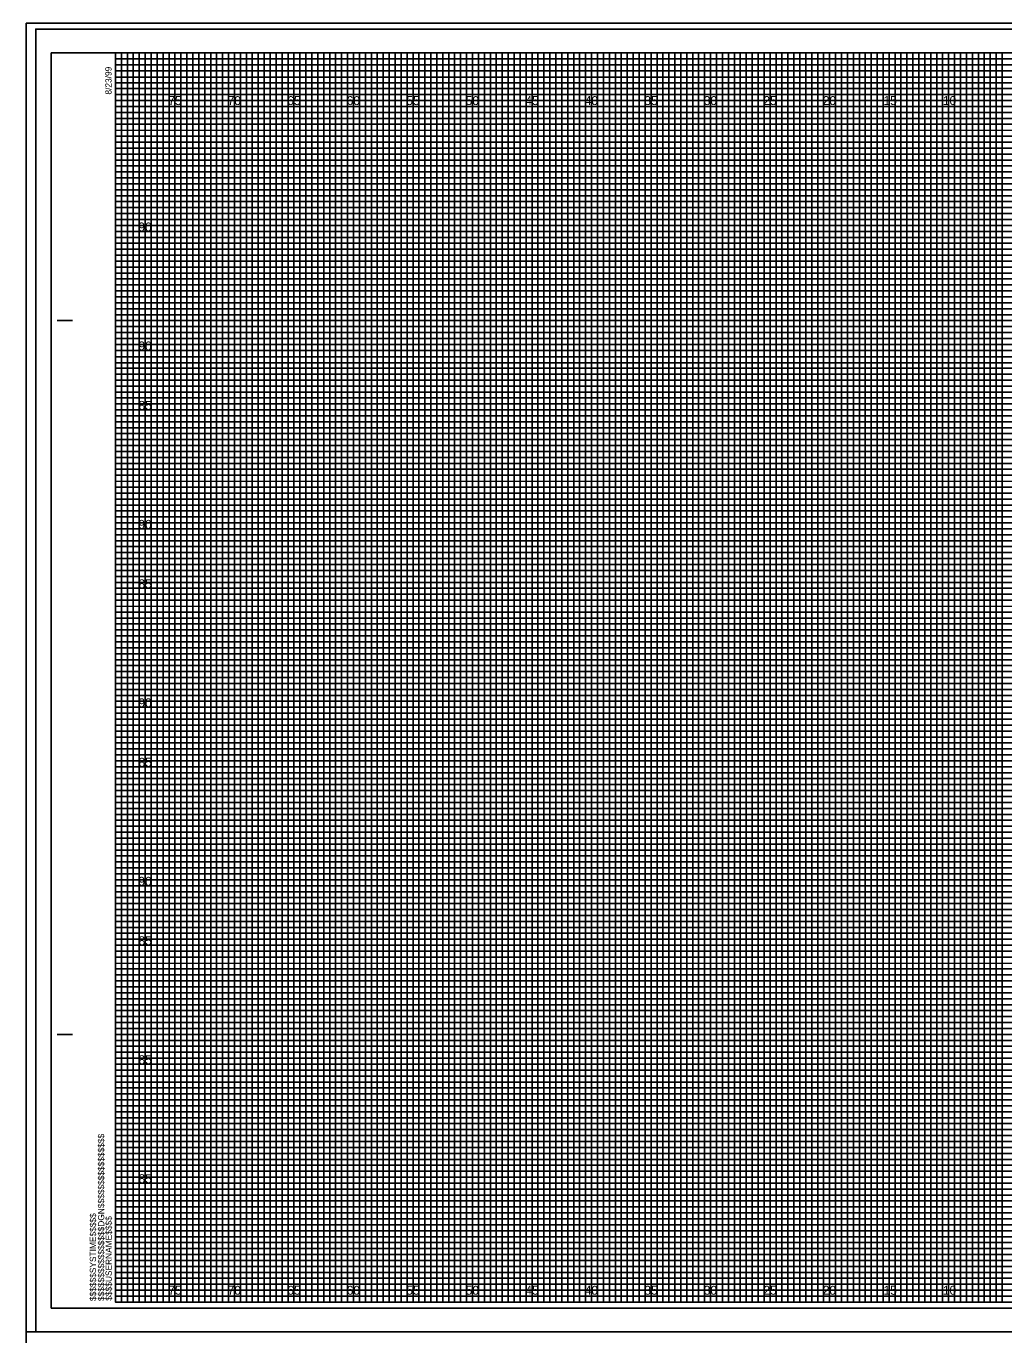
# Model space of a CAD drawing. Extents: x -8 to 533, y -20 to 768.
# Drawn here: x -7.5 to 74.6, y 547.2 to 657.2 of the extents above; entities that cross this region are included whole.
import ezdxf

# ---------------------------------------------------------------- set-up
doc = ezdxf.new("R2010")
doc.units = 0
for name, color, linetype in [('Prop XS Elevation Labels', 7, 'Continuous'), ('Prop XS Offset Labels', 7, 'Continuous'), ('Sheet Cross Section CELL', 7, 'Continuous'), ('Sheet Cross Section Grid Major CELL', 7, 'Continuous'), ('Sheet Cross Section Grid Middle CELL', 7, 'Continuous'), ('Sheet Cross Section Grid Minor 1 CELL', 7, 'Continuous'), ('Sheet Cross Section Grid Minor 2 CELL', 7, 'Continuous'), ('Sheet Cutting Line CELL', 7, 'Continuous'), ('Sheet DOT Grid CELL', 7, 'Continuous'), ('Sheet Plot Border Inside CELL', 7, 'Continuous'), ('Sheet Plot Border Outside CELL', 7, 'Continuous'), ('WEI Plot Border', 7, 'Continuous')]:
    doc.layers.add(name, color=color, linetype=linetype)

msp = doc.modelspace()

# ---------------------------------------------------------------- linework, layer by layer
at = {"layer": 'Sheet Cross Section CELL'}
for p, q in [((-4.9, 632.5), (-3.65, 632.5)), ((-4.85, 632.5), (-3.6, 632.5)), ((-4.9, 572.5), (-3.65, 572.5)), ((-4.85, 572.5), (-3.6, 572.5)), ((0, 550), (0, 550)), ((0, 550), (0, 550)), ((0, 550), (0, 550)), ((0, 550), (0, 550)), ((0, 550), (0, 550)), ((0, 550), (0, 550)), ((0, 550), (0, 550))]:
    msp.add_line(p, q, dxfattribs=at)
msp.add_lwpolyline([(160, 655), (0, 655), (0, 550), (160, 550)], close=True, dxfattribs=at)
at = {"layer": 'Sheet Cross Section Grid Major CELL'}
for p, q in [((5, 655), (0, 655)), ((5, 550), (5, 655)), ((15, 655), (10, 655)), ((10, 655), (10, 550)), ((15, 550), (15, 655)), ((25, 655), (20, 655)), ((20, 655), (20, 550)), ((25, 550), (25, 655)), ((35, 655), (30, 655)), ((30, 655), (30, 550)), ((35, 550), (35, 655)), ((45, 655), (40, 655)), ((40, 655), (40, 550)), ((45, 550), (45, 655)), ((55, 655), (50, 655)), ((50, 655), (50, 550)), ((55, 550), (55, 655)), ((65, 655), (60, 655)), ((60, 655), (60, 550)), ((65, 550), (65, 655)), ((75, 655), (70, 655)), ((70, 655), (70, 550)), ((10, 550), (5, 550)), ((20, 550), (15, 550)), ((30, 550), (25, 550)), ((40, 550), (35, 550)), ((50, 550), (45, 550)), ((60, 550), (55, 550)), ((70, 550), (65, 550))]:
    msp.add_line(p, q, dxfattribs=at)
for points in [[(0, 650), (160, 650), (160, 645), (0, 645)], [(0, 640), (160, 640), (160, 635), (0, 635)], [(0, 630), (160, 630), (160, 625), (0, 625)], [(0, 620), (160, 620), (160, 615), (0, 615)], [(0, 610), (160, 610), (160, 605), (0, 605)], [(0, 600), (160, 600), (160, 595), (0, 595)], [(0, 590), (160, 590), (160, 585), (0, 585)], [(0, 580), (160, 580), (160, 575), (0, 575)], [(0, 570), (160, 570), (160, 565), (0, 565)], [(0, 560), (160, 560), (160, 555), (0, 555)]]:
    msp.add_lwpolyline(points, dxfattribs=at)
at = {"layer": 'Sheet Cross Section Grid Middle CELL'}
for points in [[(0, 655), (2.5, 655), (2.5, 550), (7.5, 550), (7.5, 655), (12.5, 655), (12.5, 550), (17.5, 550), (17.5, 655), (22.5, 655), (22.5, 550), (27.5, 550), (27.5, 655), (32.5, 655), (32.5, 550), (37.5, 550), (37.5, 655), (42.5, 655), (42.5, 550), (47.5, 550), (47.5, 655), (52.5, 655), (52.5, 550), (57.5, 550), (57.5, 655), (62.5, 655), (62.5, 550), (67.5, 550), (67.5, 655), (72.5, 655), (72.5, 550), (77.5, 550)], [(0, 652.5), (137.5, 652.5)], [(0, 642.5), (160, 642.5), (160, 647.5), (0, 647.5)], [(0, 632.5), (160, 632.5), (160, 637.5), (0, 637.5)], [(0, 622.5), (160, 622.5), (160, 627.5), (0, 627.5)], [(0, 612.5), (160, 612.5), (160, 617.5), (0, 617.5)], [(0, 602.5), (160, 602.5), (160, 607.5), (0, 607.5)], [(0, 592.5), (160, 592.5), (160, 597.5), (0, 597.5)], [(0, 582.5), (160, 582.5), (160, 587.5), (0, 587.5)], [(0, 572.5), (160, 572.5), (160, 577.5), (0, 577.5)], [(0, 562.5), (160, 562.5), (160, 567.5), (0, 567.5)], [(0, 552.5), (160, 552.5), (160, 557.5), (0, 557.5)]]:
    msp.add_lwpolyline(points, dxfattribs=at)
at = {"layer": 'Sheet Cross Section Grid Minor 1 CELL'}
for p, q in [((0, 654.5), (130, 654.5)), ((130, 653.99), (0, 653.99)), ((0, 653.99), (0, 653.5)), ((0, 653.5), (130, 653.5)), ((130, 652.95), (0, 652.95)), ((0, 652.95), (0, 652)), ((0, 652), (160, 652))]:
    msp.add_line(p, q, dxfattribs=at)
for points in [[(0, 651.5), (135, 651.5), (160, 651.5), (160, 651), (0, 651)], [(0, 650.5), (160, 650.5), (160, 649.5), (0, 649.5)], [(0, 649), (160, 649), (160, 648.5), (0, 648.49)], [(0, 648), (160, 648), (160, 647), (0, 647)], [(0, 646.5), (160, 646.5), (160, 646), (0, 646)], [(0, 645.5), (160, 645.5), (160, 644.5), (0, 644.5)], [(0, 644), (160, 644), (160, 643.5), (0, 643.5)], [(0, 643), (160, 643), (160, 642), (0, 642)], [(0, 641.5), (160, 641.5), (160, 641), (0, 641)], [(0, 640.5), (160, 640.5), (160, 639.5), (0, 639.5)], [(0, 639), (160, 639), (160, 638.5), (0, 638.5)], [(0, 638), (160, 638), (160, 636.98), (160, 636.5), (160, 636), (0, 636)], [(0, 637), (160, 637), (160, 636.5), (0, 636.5)], [(0, 635.5), (160, 635.5), (160, 634.5), (0, 634.51)], [(0, 634.51), (160, 634.5), (160, 634), (0, 634)], [(0, 633.5), (160, 633.5), (160, 633), (0, 633)], [(0, 632), (160, 632), (160, 631.5), (0, 631.5)], [(0, 631), (160, 631), (160, 630.5), (0, 630.5)], [(-0.04, 629.45), (160, 629.45), (160, 628.94), (-0.04, 628.94)], [(0, 628.5), (160, 628.5), (160, 628), (0, 628)], [(0, 627), (160, 627), (160, 626.5), (0, 626.5)], [(0, 626), (160, 626), (160, 625.5), (0, 625.5)], [(0, 624.5), (160, 624.5), (160, 624), (0, 624)], [(0, 623.5), (160, 623.5), (160, 623), (0, 623)], [(0, 622), (160, 622), (160, 621.5), (0, 621.5)], [(0, 621), (160, 621), (160, 620.5), (0, 620.5)], [(0, 619.5), (160, 619.5), (160, 618.99), (0, 619)], [(0, 618.5), (160, 618.5), (160, 618), (0, 618)], [(0, 617), (160, 617), (160, 616.5), (0, 616.5)], [(0, 616), (160, 616), (160, 615.5), (0, 615.5)], [(0, 614.5), (160, 614.5), (160, 614), (0, 614)], [(0, 613.5), (160, 613.5), (160, 613), (0, 613)], [(0, 612), (160, 612), (160, 611.5), (0, 611.5)], [(0, 611), (160, 611), (160, 610.5), (0, 610.5)], [(0, 609.5), (160, 609.5), (160, 609), (0, 609)], [(0, 608.5), (160.03, 608.46), (160, 608), (0, 608)], [(0, 607), (160, 607), (160, 606.5), (0, 606.5)], [(0, 606), (160, 606), (160, 605.5), (0, 605.5)], [(0, 604.5), (160, 604.5), (160, 604), (0, 604)], [(0, 603.5), (160, 603.5), (160, 603), (0, 603)], [(0, 602), (160, 602), (160, 601.5), (0, 601.5)], [(0, 601), (160, 601), (160, 600.5), (0, 600.5)], [(0, 599.5), (160, 599.5), (160, 599), (0, 599)], [(0, 598.5), (160, 598.5), (160, 598), (0, 598)], [(0, 597), (160, 597), (160, 596.5), (0, 596.5)], [(0, 596), (160, 596), (160, 595.5), (0, 595.5)], [(0, 594.5), (160, 594.5), (160, 594), (0, 594)], [(0, 593.5), (160, 593.5), (160, 593), (0, 593)], [(0, 592), (160, 592), (160, 591.5), (0, 591.5)], [(0, 591), (160, 591), (160, 590.5), (0, 590.5)], [(0, 589.5), (160, 589.5), (160, 588.99), (0, 589)], [(0, 588.5), (160, 588.5), (160, 588), (0, 588)], [(0, 587), (160, 587), (160, 586.5), (0, 586.5)], [(0, 586), (160, 586), (160, 585.5), (0, 585.5)], [(0, 584.5), (160, 584.5), (160, 584), (0, 584)], [(0, 583.5), (160, 583.5), (160, 583), (0, 583)], [(0, 582), (160, 582), (160, 581.5), (0, 581.5)], [(0, 581), (160, 581), (160, 580.5), (0, 580.5)], [(0, 579.5), (160, 579.5), (160, 579), (0, 579)], [(0, 578.5), (160.03, 578.46), (160, 578), (0, 578)], [(0, 577), (160, 577), (160, 576.5), (0, 576.5)], [(0, 576), (160, 576), (160, 575.5), (0, 575.5)], [(0, 574.5), (160, 574.5), (160, 574), (0, 574)], [(0, 573.5), (160, 573.5), (160, 573), (0, 573)], [(0, 572), (160, 572), (160, 571.5), (0, 571.5)], [(0, 571), (160, 571), (160, 570.5), (0, 570.5)], [(0, 569.5), (160, 569.5), (160, 569), (0, 569)], [(0, 568.5), (160, 568.5), (160, 568), (0, 568)], [(0, 567), (160, 567), (160, 566.5), (0, 566.5)], [(0, 566), (160, 566), (160, 565.5), (0, 565.5)], [(0, 564.5), (160, 564.5), (160, 564), (0, 564)], [(0, 563.5), (160, 563.5), (160, 563), (0, 563)], [(0, 562), (160, 562), (160, 561.5), (0, 561.5)], [(0, 561), (160, 561), (160, 560.5), (0, 560.5)], [(0, 559.5), (160, 559.5), (160, 559), (0, 559)], [(0, 558.5), (160, 558.5), (160, 558), (0, 558)], [(0, 557), (160, 557), (160, 556.5), (0, 556.5)], [(0, 556), (160, 556), (160, 555.5), (0, 555.5)], [(0, 554.5), (160, 554.5), (160, 554), (0, 554)], [(0, 553.5), (160, 553.5), (160, 553), (0, 553)], [(0, 552), (160, 552), (160, 551.5), (0, 551.5)], [(0, 551), (160, 551), (160, 550.5), (0, 550.5)]]:
    msp.add_lwpolyline(points, dxfattribs=at)
at = {"layer": 'Sheet Cross Section Grid Minor 2 CELL'}
for points in [[(0, 550), (0.5, 550), (0.5, 655), (1, 655), (1, 550)], [(1, 550), (1.5, 550), (1.5, 655), (2, 655), (2, 550)], [(2.5, 550), (3, 550), (3, 655), (3.5, 655), (3.5, 550)], [(3.5, 550), (4, 550), (4, 655), (4.5, 655), (4.5, 550)], [(5, 550), (5.5, 550), (5.5, 655), (6, 655), (6, 550)], [(6, 550), (6.5, 550), (6.5, 655), (7, 655), (7, 550)], [(7.5, 550), (8, 550), (8, 655), (8.5, 655), (8.5, 550)], [(8.5, 550), (9, 550), (9, 655), (9.5, 655), (9.5, 550)], [(10, 550), (10.5, 550), (10.5, 655), (11, 655), (11, 550)], [(11, 550), (11.5, 550), (11.5, 655), (12, 655), (12, 550)], [(12.5, 550), (13, 550), (13, 655), (13.5, 655), (13.5, 550)], [(13.5, 550), (14, 550), (14, 655), (14.5, 655), (14.5, 550)], [(15, 550), (15.5, 550), (15.5, 655), (16, 655), (16, 550)], [(16, 550), (16.5, 550), (16.5, 655), (17, 655), (17, 550)], [(17.5, 550), (18, 550), (18, 655), (18.5, 655), (18.5, 550)], [(18.5, 550), (19, 550), (19, 655), (19.5, 655), (19.5, 550)], [(20, 550), (20.5, 550), (20.5, 655), (21, 655), (21, 550)], [(21, 550), (21.5, 550), (21.5, 655), (22, 655), (22, 550)], [(22.5, 550), (23, 550), (23, 655), (23.5, 655), (23.5, 550)], [(23.5, 550), (24, 550), (24, 655), (24.5, 655), (24.5, 550)], [(25, 550), (25.5, 550), (25.5, 655), (26, 655), (26, 550)], [(26, 550), (26.5, 550), (26.5, 655), (27, 655), (27, 550)], [(27.5, 550), (28, 550), (28, 655), (28.5, 655), (28.5, 550)], [(28.5, 550), (29, 550), (29, 655), (29.5, 655), (29.5, 550)], [(30, 550), (30.5, 550), (30.5, 655), (31, 655), (31, 550)], [(31, 550), (31.5, 550), (31.5, 655), (32, 655), (32, 550)], [(32.5, 550), (33, 550), (33, 655), (33.5, 655), (33.5, 550)], [(33.5, 550), (34, 550), (34, 655), (34.5, 655), (34.5, 550)], [(35, 550), (35.5, 550), (35.5, 655), (36, 655), (36, 550)], [(36, 550), (36.5, 550), (36.5, 655), (37, 655), (37, 550)], [(37.5, 550), (38, 550), (38, 655), (38.5, 655), (38.5, 550)], [(38.5, 550), (39, 550), (39, 655), (39.5, 655), (39.5, 550)], [(40, 550), (40.5, 550), (40.5, 655), (41, 655), (41, 550)], [(41, 550), (41.5, 550), (41.5, 655), (42, 655), (42, 550)], [(42.5, 550), (43, 550), (43, 655), (43.5, 655), (43.5, 550)], [(43.5, 550), (44, 550), (44, 655), (44.5, 655), (44.5, 550)], [(45, 550), (45.5, 550), (45.5, 655), (46, 655), (46, 550)], [(46, 550), (46.5, 550), (46.5, 655), (47, 655), (47, 550)], [(47.5, 550), (48, 550), (48, 655), (48.5, 655), (48.5, 550)], [(48.5, 550), (49, 550), (49, 655), (49.5, 655), (49.5, 550)], [(50, 550), (50.5, 550), (50.5, 655), (51, 655), (51, 550)], [(51, 550), (51.5, 550), (51.5, 655), (52, 655), (52, 550)], [(52.5, 550), (53, 550), (53, 655), (53.5, 655), (53.5, 550)], [(53.5, 550), (54, 550), (54, 655), (54.5, 655), (54.5, 550)], [(55, 550), (55.5, 550), (55.5, 655), (56, 655), (56, 550)], [(56, 550), (56.5, 550), (56.5, 655), (57, 655), (57, 550)], [(57.5, 550), (58, 550), (58, 655), (58.5, 655), (58.5, 550)], [(58.5, 550), (59, 550), (59, 655), (59.5, 655), (59.5, 550)], [(60, 550), (60.5, 550), (60.5, 655), (61, 655), (61, 550)], [(61, 550), (61.5, 550), (61.5, 655), (62, 655), (62, 550)], [(62.5, 550), (63, 550), (63, 655), (63.5, 655), (63.5, 550)], [(63.5, 550), (64, 550), (64, 655), (64.5, 655), (64.5, 550)], [(65, 550), (65.5, 550), (65.5, 655), (66, 655), (66, 550)], [(66, 550), (66.5, 550), (66.5, 655), (67, 655), (67, 550)], [(67.5, 550), (68, 550), (68, 655), (68.5, 655), (68.5, 550)], [(68.5, 550), (69, 550), (69, 655), (69.5, 655), (69.5, 550)], [(70, 550), (70.5, 550), (70.5, 655), (71, 655), (71, 550)], [(71, 550), (71.5, 550), (71.5, 655), (72, 655), (72, 550)], [(72.5, 550), (73, 550), (73, 655), (73.5, 655), (73.5, 550)], [(73.5, 550), (74, 550), (74, 655), (74.5, 655), (74.5, 550)]]:
    msp.add_lwpolyline(points, dxfattribs=at)
at = {"layer": 'Sheet Cutting Line CELL'}
for p, q in [((161.65, 657), (-6.7, 657)), ((-6.7, 657), (-6.7, 547.5)), ((-6.7, 547.5), (161.65, 547.5))]:
    msp.add_line(p, q, dxfattribs=at)
at = {"layer": 'Sheet DOT Grid CELL'}
for p, q in [((5, 550), (5, 655)), ((10, 550), (10, 655)), ((15, 550), (15, 655)), ((20, 550), (20, 655)), ((25, 550), (25, 655)), ((30, 550), (30, 655)), ((35, 550), (35, 655)), ((40, 550), (40, 655)), ((45, 550), (45, 655)), ((50, 550), (50, 655)), ((55, 550), (55, 655)), ((60, 550), (60, 655)), ((65, 550), (65, 655)), ((70, 550), (70, 655)), ((0, 650), (160, 650)), ((0, 645), (160, 645)), ((0, 640), (160, 640)), ((0, 635), (160, 635)), ((0, 630), (160, 630)), ((0, 625), (160, 625)), ((0, 620), (160, 620)), ((0, 615), (160, 615)), ((0, 610), (160, 610)), ((0, 605), (160, 605)), ((0, 600), (160, 600)), ((0, 595), (160, 595)), ((0, 590), (160, 590)), ((0, 585), (160, 585)), ((0, 580), (160, 580)), ((0, 575), (160, 575)), ((0, 570), (160, 570)), ((0, 565), (160, 565)), ((0, 560), (160, 560)), ((0, 555), (160, 555))]:
    msp.add_line(p, q, dxfattribs=at)
at = {"layer": 'Sheet Plot Border Inside CELL'}
msp.add_lwpolyline([(-5.4, 549.5), (161.2, 549.5), (161.2, 655), (-5.4, 655)], close=True, dxfattribs=at)
at = {"layer": 'Sheet Plot Border Outside CELL'}
msp.add_lwpolyline([(-6.7, 547.5), (161.65, 547.5), (161.65, 657), (-6.7, 657)], close=True, dxfattribs=at)
at = {"layer": 'WEI Plot Border'}
for points in [[(-7.5, 547.5), (162.5, 547.5), (162.5, 657.5), (-7.5, 657.5)], [(-7.5, 437.5), (162.5, 437.5), (162.5, 547.5), (-7.5, 547.5)]]:
    msp.add_lwpolyline(points, close=True, dxfattribs=at)

# ---------------------------------------------------------------- texts
at = {"layer": 'Prop XS Elevation Labels'}
for s, p in [('90', (1.93, 640)), ('90', (1.93, 630)), ('85', (1.94, 625)), ('90', (1.93, 615)), ('85', (1.94, 610)), ('90', (1.93, 600)), ('85', (1.94, 595)), ('90', (1.93, 585)), ('85', (1.94, 580)), ('85', (1.94, 570)), ('85', (1.94, 560))]:
    msp.add_text(s, height=0.75, dxfattribs=at).set_placement(p)
at = {"layer": 'Prop XS Offset Labels'}
for s, p in [('75', (4.44, 650.62)), ('70', (9.43, 650.62)), ('65', (14.44, 650.62)), ('60', (19.43, 650.62)), ('55', (24.44, 650.62)), ('50', (29.43, 650.62)), ('45', (34.44, 650.62)), ('40', (39.43, 650.62)), ('35', (44.44, 650.62)), ('30', (49.43, 650.62)), ('25', (54.44, 650.62)), ('20', (59.43, 650.62)), ('15', (64.53, 650.62)), ('10', (69.52, 650.62)), ('75', (4.44, 550.62)), ('70', (9.43, 550.62)), ('65', (14.44, 550.62)), ('60', (19.43, 550.62)), ('55', (24.44, 550.62)), ('50', (29.43, 550.62)), ('45', (34.44, 550.62)), ('40', (39.43, 550.62)), ('35', (44.44, 550.62)), ('30', (49.43, 550.62)), ('25', (54.44, 550.62)), ('20', (59.43, 550.62)), ('15', (64.53, 550.62)), ('10', (69.52, 550.62))]:
    msp.add_text(s, height=0.75, dxfattribs=at).set_placement(p)
at = {"layer": 'Sheet Cross Section CELL'}
for s, p in [('8/23/99', (-0.33, 651.5)), ('$$$$$$$$$$$$$$$$DGN$$$$$$$$$$$$$$$$', (-0.94, 550.09)), ('$$$$$$SYSTIME$$$$$', (-1.63, 550.09)), ('$$$$USERNAME$$$$', (-0.31, 550.12))]:
    msp.add_text(s, height=0.525, rotation=90, dxfattribs=at).set_placement(p)

doc.saveas('drawing.dxf')
